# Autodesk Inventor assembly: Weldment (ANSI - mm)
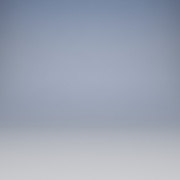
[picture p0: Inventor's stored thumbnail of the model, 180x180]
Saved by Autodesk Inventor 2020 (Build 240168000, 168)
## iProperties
Length Units: 11269
Angle Units: 11283
Time Units: 11279
Mass Units: 11290
Length Display Precision: 3
Angle Display Precision: 2
Part Number: Weldment (ANSI - mm)
Document SubType Name: Weldment
Created: 2002-06
Designer: smithga
Created: 2002-08
Designer: F.Stasiak
Weld Material: Welded Aluminum-6061
Manager: www.cadconsulting.pl
Company: Fabian Stasiak CAD Consulting
Control State: 0
Master: False
Shininess: 64.0
Angle Units: 11279
Time Units: 11290
Mass Units: 11283
Compacted: True
Density: 0.0
Volumn: 0.0
Area: 0.0
PropertySet Name: Model Information
Author: F.Stasiak
Subject: Zbiór ćwiczeń. Autodesk Inventor 2020. Kurs podstawowy
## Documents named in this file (1)
- M:\AUTOBUILD\M24_168_RTM\Application\App\Templates\en-US\Metric\Weldment (ANSI - mm).iam
